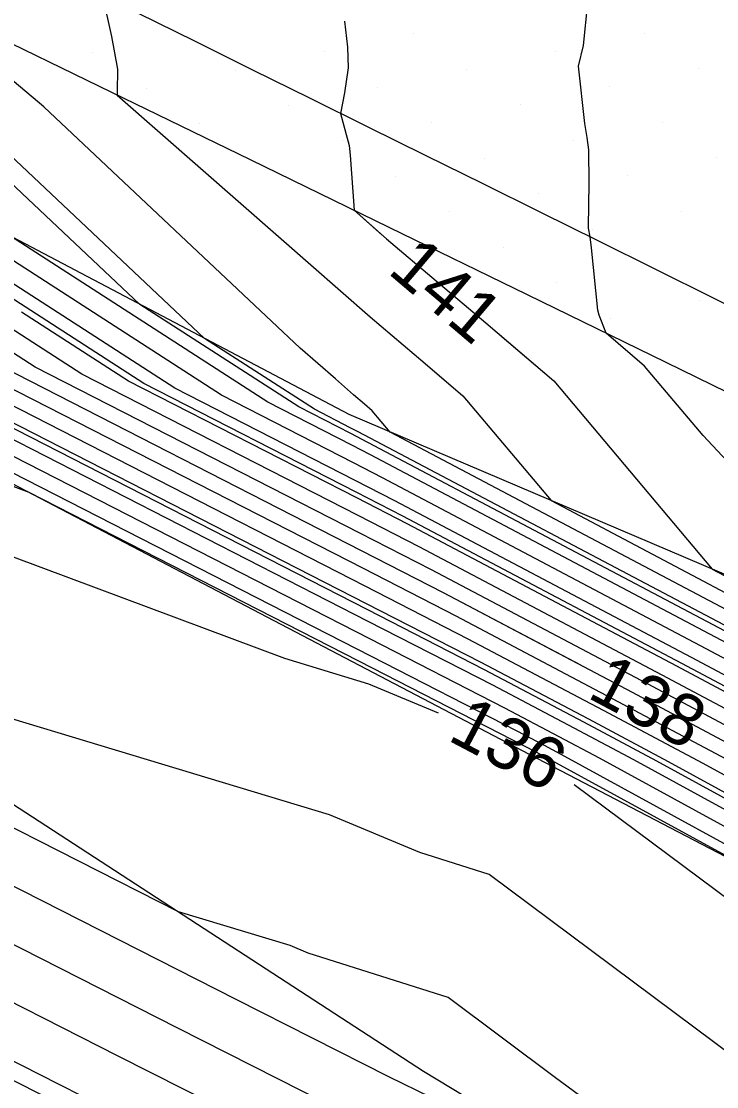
# Model space of a CAD drawing. Extents: x 2354170 to 2357230, y 866100 to 868290.
# Drawn here: x 2355011.89 to 2355038.97, y 867493.84 to 867535.31 of the extents above; entities that cross this region are included whole.
import ezdxf

# ---------------------------------------------------------------- set-up
doc = ezdxf.new("R2010")
doc.units = 0
for name, color, linetype in [('Default', 7, 'Continuous'), ('DTM Contours Major', 7, 'Continuous'), ('DTM Contours Minor', 7, 'Continuous'), ('Exist DTM Breakline', 7, 'Continuous'), ('Exist DTM Scan Elevation Point', 7, 'Continuous'), ('Exist Roads EOP', 7, 'Continuous'), ('PH Exist DTM Breakline', 7, 'Continuous')]:
    doc.layers.add(name, color=color, linetype=linetype)

msp = doc.modelspace()

# ---------------------------------------------------------------- linework, layer by layer
at = {"layer": 'Default'}
for points in [[(2355033.678, 867510.247), (2355028.337, 867513.069), (2355025.14, 867514.703), (2355010.629, 867522.123), (2355002.336, 867527.472), (2354993.032, 867532.909), (2354982.415, 867538.37), (2354973.577, 867543.373), (2354967.708, 867546.59), (2354952.204, 867554.879), (2354946.731, 867557.91), (2354946.064, 867558.354)], [(2355028.14, 867508.38), (2355025.43, 867509.516), (2355022.157, 867510.504), (2354997.995, 867519.526), (2354982.848, 867522.426), (2354981.139, 867522.653), (2354962.741, 867534.171), (2354961.893, 867534.749), (2354950.187, 867542.514), (2354948.017, 867546.285), (2354940.864, 867552.649)], [(2355078.753, 867490.443), (2355061.657, 867499.74), (2355060.275, 867500.496), (2355056.807, 867502.382), (2355050.536, 867505.811), (2355039.711, 867511.57), (2355025.013, 867519.335), (2355024.705, 867519.492), (2355023.308, 867520.206), (2355019.029, 867522.966), (2355010.053, 867531.404), (2355007.956, 867533.167), (2355004.736, 867535.657), (2354999.605, 867539.745), (2354998.873, 867540.31), (2354998.068, 867540.964), (2354997.608, 867542.034), (2354997.499, 867542.452), (2354997.186, 867543.475), (2354996.752, 867545.077)], [(2355015.061, 867536.302), (2355015.402, 867534.719), (2355015.635, 867533.45), (2355015.622, 867532.559), (2355015.623, 867532.462), (2355015.621, 867532.436), (2355022.01, 867526.837), (2355025.471, 867523.808), (2355027.62, 867521.987), (2355029.091, 867520.729), (2355032.524, 867516.655), (2355040.858, 867512.252), (2355053.228, 867505.672), (2355056.584, 867503.837), (2355060.584, 867501.662), (2355061.388, 867501.222), (2355081.358, 867490.362)], [(2355041.974, 867515.414), (2355038.44, 867519.182), (2355036.159, 867521.888), (2355034.666, 867523.165), (2355034.393, 867523.875), (2355034.343, 867524.071), (2355034.089, 867526.487), (2355034.041, 867526.916), (2355033.982, 867527.262), (2355033.983, 867527.307), (2355034.002, 867528.999), (2355033.985, 867530.303), (2355033.932, 867530.789), (2355033.836, 867531.325), (2355033.591, 867533.561), (2355033.778, 867534.365), (2355033.951, 867536.029)], [(2355024.481, 867535.309), (2355024.598, 867534.3), (2355024.619, 867533.502), (2355024.476, 867532.521), (2355024.322, 867531.726), (2355024.587, 867530.754), (2355024.656, 867530.48), (2355024.696, 867530.099), (2355024.851, 867527.952), (2355025.95, 867526.989)], [(2355152.49, 867449.764), (2355149.162, 867451.689), (2355139.515, 867457.648), (2355129.507, 867463.442), (2355112.774, 867472.437), (2355112.56, 867472.554), (2355103.265, 867477.646), (2355097.879, 867480.538), (2355088.526, 867485.764), (2355080.146, 867490.353), (2355061.522, 867500.481), (2355060.429, 867501.079), (2355056.695, 867503.109), (2355051.882, 867505.741), (2355040.285, 867511.911), (2355026.253, 867519.323), (2355025.557, 867520.149), (2355025.259, 867520.405), (2355024.823, 867520.774), (2355024.122, 867521.388), (2355022.753, 867522.587), (2355012.766, 867531.975), (2355009.539, 867534.688)], [(2355147.783, 867450.44), (2355140.068, 867455.205), (2355126.908, 867462.824), (2355113.442, 867470.063), (2355113.148, 867470.224), (2355100.43, 867477.191), (2355096.152, 867479.488), (2355088.722, 867483.639), (2355076.511, 867490.327), (2355061.926, 867498.259), (2355059.966, 867499.331), (2355057.031, 867500.926), (2355047.845, 867505.95), (2355038.564, 867510.887), (2355025.962, 867517.544), (2355024.829, 867518.124), (2355019.685, 867520.754), (2355004.941, 867530.263)], [(2355147.323, 867450.023), (2355140.252, 867454.391), (2355126.042, 867462.618), (2355113.665, 867469.271), (2355113.345, 867469.447), (2355099.485, 867477.039), (2355095.576, 867479.138), (2355088.787, 867482.931), (2355075.3, 867490.318), (2355062.061, 867497.518), (2355059.812, 867498.748), (2355057.143, 867500.199), (2355046.499, 867506.019), (2355037.991, 867510.546), (2355026.437, 867516.649), (2355024.891, 867517.44), (2355017.874, 867521.028), (2355004.42, 867529.705)], [(2355146.404, 867449.191), (2355140.621, 867452.763), (2355124.309, 867462.206), (2355114.11, 867467.689), (2355113.737, 867467.893), (2355097.596, 867476.735), (2355094.425, 867478.438), (2355088.917, 867481.515), (2355072.876, 867490.301), (2355062.33, 867496.036), (2355059.503, 867497.582), (2355057.367, 867498.744), (2355043.808, 867506.158), (2355036.844, 867509.863), (2355027.387, 867514.859), (2355025.015, 867516.072), (2355014.251, 867521.576), (2355003.378, 867528.588)], [(2355145.944, 867448.774), (2355140.805, 867451.948), (2355123.443, 867462), (2355114.333, 867466.897), (2355113.933, 867467.116), (2355096.651, 867476.584), (2355093.849, 867478.088), (2355088.983, 867480.807), (2355071.665, 867490.292), (2355062.464, 867495.295), (2355059.349, 867496.999), (2355057.478, 867498.016), (2355042.463, 867506.228), (2355036.27, 867509.522), (2355027.862, 867513.964), (2355025.078, 867515.388), (2355012.44, 867521.849), (2355002.857, 867528.03)], [(2355148.243, 867450.856), (2355139.884, 867456.019), (2355127.774, 867463.03), (2355113.22, 867470.854), (2355112.952, 867471.001), (2355101.375, 867477.343), (2355096.728, 867479.838), (2355088.656, 867484.347), (2355077.723, 867490.336), (2355061.791, 867499), (2355060.121, 867499.913), (2355056.919, 867501.654), (2355049.191, 867505.88), (2355039.138, 867511.228), (2355025.488, 867518.439), (2355024.767, 867518.808), (2355021.497, 867520.48), (2355011.48, 867526.94)], [(2355099.74, 867476.23), (2355098.541, 867476.887), (2355095, 867478.788), (2355088.852, 867482.223), (2355074.088, 867490.31), (2355062.195, 867496.777), (2355059.658, 867498.165), (2355057.255, 867499.471), (2355045.154, 867506.089), (2355037.417, 867510.204), (2355026.912, 867515.754), (2355024.953, 867516.756), (2355016.063, 867521.302), (2355011.901, 867523.985)], [(2354999.761, 867523.766), (2355025.512, 867510.599), (2355031.186, 867507.698), (2355032.255, 867507.133), (2355033.043, 867506.714), (2355058.261, 867492.923), (2355058.268, 867492.92), (2355058.958, 867492.542), (2355062.857, 867489.646), (2355063.618, 867489.086), (2355069.09, 867486.996), (2355089.439, 867475.85), (2355089.818, 867475.638), (2355090.036, 867475.521), (2355115.307, 867461.678), (2355115.891, 867461.358), (2355117.378, 867460.558), (2355142.095, 867446.249)], [(2355001.573, 867523.493), (2355025.45, 867511.283), (2355030.711, 867508.593), (2355032.829, 867507.474), (2355034.389, 867506.645), (2355058.15, 867493.651), (2355058.423, 867493.502), (2355063.272, 867490.851), (2355064.395, 867490.24), (2355089.374, 867476.558), (2355090.394, 867475.988), (2355090.981, 867475.673), (2355115.111, 867462.455), (2355115.668, 867462.149), (2355118.245, 867460.764), (2355141.911, 867447.063)], [(2355003.384, 867523.219), (2355025.388, 867511.967), (2355030.236, 867509.488), (2355033.402, 867507.816), (2355035.734, 867506.575), (2355058.038, 867494.378), (2355058.577, 867494.085), (2355063.137, 867491.591), (2355065.607, 867490.248), (2355089.309, 867477.266), (2355090.97, 867476.338), (2355091.926, 867475.825), (2355114.915, 867463.232), (2355115.446, 867462.941), (2355119.111, 867460.97), (2355141.726, 867447.877)], [(2355030.524, 867523.106), (2355032.625, 867521.309), (2355038.795, 867513.986), (2355041.432, 867512.593), (2355054.573, 867505.602), (2355056.472, 867504.564), (2355060.738, 867502.245), (2355061.253, 867501.963), (2355082.569, 867490.371), (2355088.396, 867487.18), (2355099.031, 867481.238), (2355105.155, 867477.95), (2355112.167, 867474.108), (2355112.329, 867474.019), (2355115.821, 867472.142)], [(2355007.006, 867522.671), (2355025.264, 867513.335), (2355029.286, 867511.278), (2355034.549, 867508.498), (2355038.426, 867506.436), (2355057.814, 867495.834), (2355058.886, 867495.251), (2355062.868, 867493.073), (2355068.03, 867490.266), (2355089.178, 867478.683), (2355092.121, 867477.038), (2355093.816, 867476.128), (2355114.522, 867464.785), (2355115.001, 867464.523), (2355120.844, 867461.382), (2355141.358, 867449.506)], [(2355008.818, 867522.397), (2355025.202, 867514.019), (2355028.812, 867512.174), (2355035.123, 867508.839), (2355039.771, 867506.367), (2355057.702, 867496.561), (2355059.04, 867495.834), (2355062.733, 867493.814), (2355069.242, 867490.275), (2355089.113, 867479.391), (2355092.697, 867477.388), (2355094.761, 867476.28), (2355114.326, 867465.562), (2355114.778, 867465.315), (2355121.71, 867461.588), (2355141.174, 867450.32)], [(2355008.576, 867521.216), (2355025.326, 867512.651), (2355029.761, 867510.383), (2355033.976, 867508.157), (2355037.08, 867506.506), (2355057.926, 867495.106), (2355058.731, 867494.668), (2355063.003, 867492.332), (2355066.818, 867490.257), (2355089.243, 867477.974), (2355091.546, 867476.688), (2355092.871, 867475.977), (2355096.664, 867473.899)], [(2355206.008, 867399.059), (2355189.238, 867406.695), (2355183.856, 867411.301), (2355180.367, 867413.581), (2355176.811, 867415.677), (2355162.994, 867424.674), (2355150.813, 867431.854), (2355146.001, 867435.425), (2355142.145, 867438.036), (2355133.228, 867444.605), (2355116.039, 867456.096), (2355115.566, 867456.273), (2355108.587, 867458.998), (2355091.507, 867465.444), (2355074.831, 867472.029), (2355066.453, 867475.23), (2355056.492, 867482.561), (2355054.949, 867483.707), (2355041.295, 867493.758), (2355030.106, 867502.097), (2355027.412, 867502.954), (2355023.898, 867504.427), (2355002.064, 867511.013)], [(2355115.558, 867449.59), (2355097.876, 867456.495), (2355092.947, 867458.355), (2355078.344, 867464.121), (2355067.397, 867469.793), (2355054.41, 867478.207), (2355053.309, 867479.018), (2355053.269, 867479.047), (2355032.699, 867494.191), (2355028.51, 867497.313), (2355023.066, 867499.044), (2355022.365, 867499.338), (2355018.011, 867500.651), (2354998.598, 867510.504)], [(2355076.434, 867457.476), (2355066.558, 867462.592), (2355059.24, 867467.334), (2355046.819, 867474.942), (2355043.187, 867477.166), (2355030.023, 867485.74), (2355016.136, 867492.529), (2355013.372, 867493.932), (2355003.921, 867498.728), (2354992.688, 867504.16), (2354989.081, 867505.866)], [(2355090.238, 867456.051), (2355067.187, 867467.993), (2355054.698, 867476.085), (2355051.655, 867477.949), (2355050.765, 867478.494), (2355027.846, 867493.422), (2355026.207, 867494.223), (2355020.26, 867497.241), (2355003.584, 867505.705)], [(2355120.528, 867458.027), (2355116.512, 867460.352), (2355116.114, 867460.567), (2355115.503, 867460.901), (2355103.575, 867467.435), (2355090.067, 867472.533), (2355085.228, 867474.444), (2355065.036, 867482.158), (2355059.674, 867486.103), (2355056.628, 867488.366), (2355049.891, 867493.326), (2355033.424, 867505.598)], [(2355206.096, 867387.294), (2355185.909, 867398.139), (2355178.94, 867402.004), (2355174.728, 867404.556), (2355173.329, 867405.33), (2355154.767, 867416.578), (2355149.648, 867419.858), (2355142.273, 867424.313), (2355136.401, 867427.874), (2355115.792, 867440.318), (2355114.362, 867441.184), (2355096.389, 867450.283), (2355091.031, 867453.482), (2355087.865, 867455.371), (2355066.977, 867466.192), (2355056.212, 867473.168), (2355050.043, 867476.946), (2355048.239, 867478.051), (2355028.572, 867490.861), (2355022.85, 867493.658), (2355017.964, 867496.138), (2355001.26, 867504.616)], [(2355203.95, 867386.004), (2355186.849, 867395.191), (2355176.771, 867400.781), (2355173.32, 867402.872), (2355171.283, 867403.999), (2355156.186, 867413.147), (2355148.501, 867418.072), (2355142.442, 867421.732), (2355133.164, 867427.358), (2355116.033, 867437.702), (2355113.183, 867439.43), (2355098.181, 867447.024), (2355089.462, 867452.229), (2355084.311, 867455.304), (2355066.768, 867464.392), (2355057.726, 867470.251), (2355048.431, 867475.944), (2355045.713, 867477.609), (2355029.297, 867488.301), (2355019.493, 867493.093), (2355015.668, 867495.035), (2355002.591, 867501.672)]]:
    msp.add_lwpolyline(points, dxfattribs=at)
at = {"layer": 'DTM Contours Major'}
for points in [[(2355092.651, 867482.563), (2355088.613, 867484.819), (2355078.531, 867490.342), (2355061.702, 867499.493), (2355060.223, 867500.302), (2355056.845, 867502.139), (2355050.088, 867505.834), (2355039.52, 867511.456), (2355025.171, 867519.036), (2355024.726, 867519.264), (2355022.704, 867520.298), (2355016.513, 867524.29), (2355009.148, 867531.213), (2355007.428, 867532.66), (2355006.796, 867533.148)], [(2355090.238, 867456.051), (2355067.187, 867467.993), (2355054.698, 867476.085), (2355051.655, 867477.949), (2355050.765, 867478.494), (2355027.846, 867493.422), (2355026.207, 867494.223), (2355020.26, 867497.241), (2355003.584, 867505.705)]]:
    msp.add_lwpolyline(points, dxfattribs=at)
at = {"layer": 'DTM Contours Minor'}
for points in [[(2354915.826, 867572.429), (2354919.657, 867570.537), (2354924.561, 867567.797), (2354934.524, 867561.906), (2354939.151, 867558.822), (2354953.971, 867550.616), (2354959.594, 867547.609), (2354973.399, 867540.041), (2354975.838, 867538.661), (2354996.12, 867528.228), (2355000.599, 867525.611), (2355004.591, 867523.036), (2355025.347, 867512.423), (2355029.92, 867510.085), (2355033.785, 867508.043), (2355036.631, 867506.529), (2355057.963, 867494.863), (2355058.68, 867494.474), (2355063.047, 867492.085), (2355066.414, 867490.254), (2355078.597, 867483.582)], [(2355024.481, 867535.309), (2355024.598, 867534.3), (2355024.619, 867533.502), (2355024.476, 867532.521), (2355024.322, 867531.726), (2355024.587, 867530.754), (2355024.656, 867530.48), (2355024.696, 867530.099), (2355024.851, 867527.952), (2355026.119, 867526.842), (2355029.982, 867523.57), (2355032.625, 867521.309), (2355038.795, 867513.986), (2355041.432, 867512.593), (2355054.573, 867505.602), (2355056.472, 867504.564), (2355060.738, 867502.245), (2355061.253, 867501.963), (2355082.569, 867490.371)], [(2354971.832, 867530.042), (2354980.053, 867524.895), (2354992.242, 867523.274), (2354998.573, 867522.062), (2355012.182, 867516.981), (2355025.554, 867510.143), (2355031.502, 867507.101), (2355031.873, 867506.905), (2355032.146, 867506.76), (2355041.126, 867501.85), (2355052.757, 867493.182), (2355057.188, 867489.919), (2355060.735, 867487.284), (2355064.563, 867484.467), (2355088.693, 867475.249), (2355089.586, 867474.897), (2355092.08, 867473.956), (2355115.438, 867461.16), (2355116.039, 867460.83), (2355116.801, 867460.421), (2355142.218, 867445.706), (2355142.419, 867445.582), (2355149.295, 867441.604)], [(2355055.238, 867500.796), (2355045.602, 867506.066), (2355037.608, 867510.318), (2355026.754, 867516.052), (2355024.933, 867516.984), (2355016.667, 867521.21), (2355004.073, 867529.333)], [(2355183.506, 867425.878), (2355178.766, 867428.672), (2355172.701, 867432.697), (2355153.401, 867444.073), (2355153.375, 867444.09), (2355150.911, 867445.218), (2355145.484, 867448.358), (2355140.989, 867451.134), (2355122.576, 867461.794), (2355114.555, 867466.106), (2355114.13, 867466.339), (2355095.706, 867476.432), (2355093.273, 867477.738), (2355089.048, 867480.099), (2355070.453, 867490.283), (2355062.599, 867494.555), (2355059.194, 867496.416), (2355057.59, 867497.289), (2355041.117, 867506.297), (2355035.697, 867509.181), (2355028.337, 867513.069), (2355025.14, 867514.703), (2355010.629, 867522.123), (2355008.889, 867523.245)], [(2355020.182, 867489.816), (2355015.017, 867492.34), (2355012.606, 867493.564), (2355004.365, 867497.747)]]:
    msp.add_lwpolyline(points, dxfattribs=at)
at = {"layer": 'Exist DTM Breakline'}
msp.add_lwpolyline([(2355041.079, 867523.426), (2355038.839, 867524.537), (2355036.599, 867525.648), (2355034.36, 867526.758), (2355032.119, 867527.868), (2355029.879, 867528.977), (2355027.638, 867530.086), (2355025.397, 867531.194), (2355023.156, 867532.302), (2355020.915, 867533.41), (2355018.674, 867534.517), (2355016.432, 867535.624)], dxfattribs=at)
at = {"layer": 'Exist DTM Scan Elevation Point'}
for p, q in [((2355027.156, 867534.821), (2355027.156, 867534.821)), ((2355036.17, 867534.852), (2355036.17, 867534.852)), ((2355014.678, 867534.084), (2355014.678, 867534.084)), ((2355023.692, 867534.115), (2355023.692, 867534.115)), ((2355032.706, 867534.147), (2355032.706, 867534.147)), ((2355020.227, 867533.41), (2355020.227, 867533.41)), ((2355029.241, 867533.441), (2355029.241, 867533.441)), ((2355038.255, 867533.473), (2355038.255, 867533.473)), ((2355016.763, 867532.704), (2355016.763, 867532.704)), ((2355025.777, 867532.736), (2355025.777, 867532.736)), ((2355034.791, 867532.767), (2355034.791, 867532.767)), ((2355022.312, 867532.03), (2355022.312, 867532.03)), ((2355031.326, 867532.062), (2355031.326, 867532.062)), ((2355018.848, 867531.325), (2355018.848, 867531.325)), ((2355027.862, 867531.356), (2355027.862, 867531.356)), ((2355036.876, 867531.388), (2355036.876, 867531.388)), ((2355024.397, 867530.651), (2355024.397, 867530.651)), ((2355033.411, 867530.682), (2355033.411, 867530.682)), ((2355029.947, 867529.977), (2355029.947, 867529.977)), ((2355038.96, 867530.009), (2355038.96, 867530.009)), ((2355026.482, 867529.271), (2355026.482, 867529.271)), ((2355035.496, 867529.303), (2355035.496, 867529.303)), ((2355032.032, 867528.597), (2355032.032, 867528.597)), ((2355028.567, 867527.892), (2355028.567, 867527.892)), ((2355037.581, 867527.924), (2355037.581, 867527.924)), ((2355034.117, 867527.218), (2355034.117, 867527.218)), ((2355030.652, 867526.513), (2355030.652, 867526.513)), ((2355032.737, 867525.133), (2355032.737, 867525.133)), ((2355038.287, 867524.459), (2355038.287, 867524.459)), ((2355034.822, 867523.754), (2355034.822, 867523.754))]:
    msp.add_line(p, q, dxfattribs=at)
at = {"layer": 'Exist Roads EOP'}
msp.add_lwpolyline([(2355080.078, 867500.856), (2355074.697, 867503.51), (2355069.314, 867506.161), (2355063.931, 867508.811), (2355058.547, 867511.46), (2355053.162, 867514.105), (2355047.776, 867516.749), (2355042.388, 867519.389), (2355036.999, 867522.026), (2355031.607, 867524.659), (2355026.214, 867527.288), (2355020.818, 867529.913), (2355015.421, 867532.533), (2355010.023, 867535.152)], dxfattribs=at)
at = {"layer": 'PH Exist DTM Breakline'}
for points in [[(2355280.46, 867391.235), (2355274.142, 867395.519), (2355265.394, 867401.62), (2355259.051, 867405.124), (2355247.649, 867410.373), (2355235.138, 867416.592), (2355206.737, 867431.244), (2355191.277, 867438.296), (2355164.634, 867452.269), (2355154.996, 867456.973), (2355137.76, 867465.404), (2355102.312, 867483.232), (2355088.098, 867490.411), (2355056.326, 867505.512), (2355041.697, 867512.751), (2355024.659, 867520.002), (2355005.016, 867530.343)], [(2354998.987, 867523.883), (2355031.67, 867506.785), (2355063.384, 867490.232), (2355116.195, 867460.277), (2355149.553, 867441.314), (2355183.938, 867421.048), (2355201.572, 867411.115), (2355224.818, 867398.158), (2355251.509, 867383.227), (2355269.376, 867369.298), (2355287.251, 867347.908), (2355294.287, 867327.619), (2355296.523, 867319.456), (2355299.911, 867295.631), (2355302.764, 867267.241), (2355304.13, 867236.824), (2355305.048, 867209.593), (2355306.062, 867178.614), (2355306.867, 867134.639), (2355307.678, 867102.256), (2355309.303, 867062.926), (2355310.069, 867028.808), (2355310.233, 866999.689)], [(2354996.831, 867514.414), (2355027.555, 867494.45), (2355067.458, 867470.316), (2355115.549, 867442.95), (2355151.936, 867423.42), (2355183.801, 867404.746), (2355224.702, 867380.361), (2355253.602, 867357.834), (2355263.9, 867342.784), (2355274.845, 867316.014), (2355275.719, 867309.171), (2355280.403, 867284.339)]]:
    msp.add_lwpolyline(points, dxfattribs=at)

# ---------------------------------------------------------------- texts
at = {"layer": 'Default'}
for s, rotation, p in [('141', 319.6701, (2355026.113, 867525.539)), ('138', 332.0508, (2355033.879, 867509.012)), ('136', 332.233, (2355028.443, 867507.355))]:
    msp.add_text(s, height=2, rotation=rotation, dxfattribs=at).set_placement(p)

doc.saveas('drawing.dxf')
